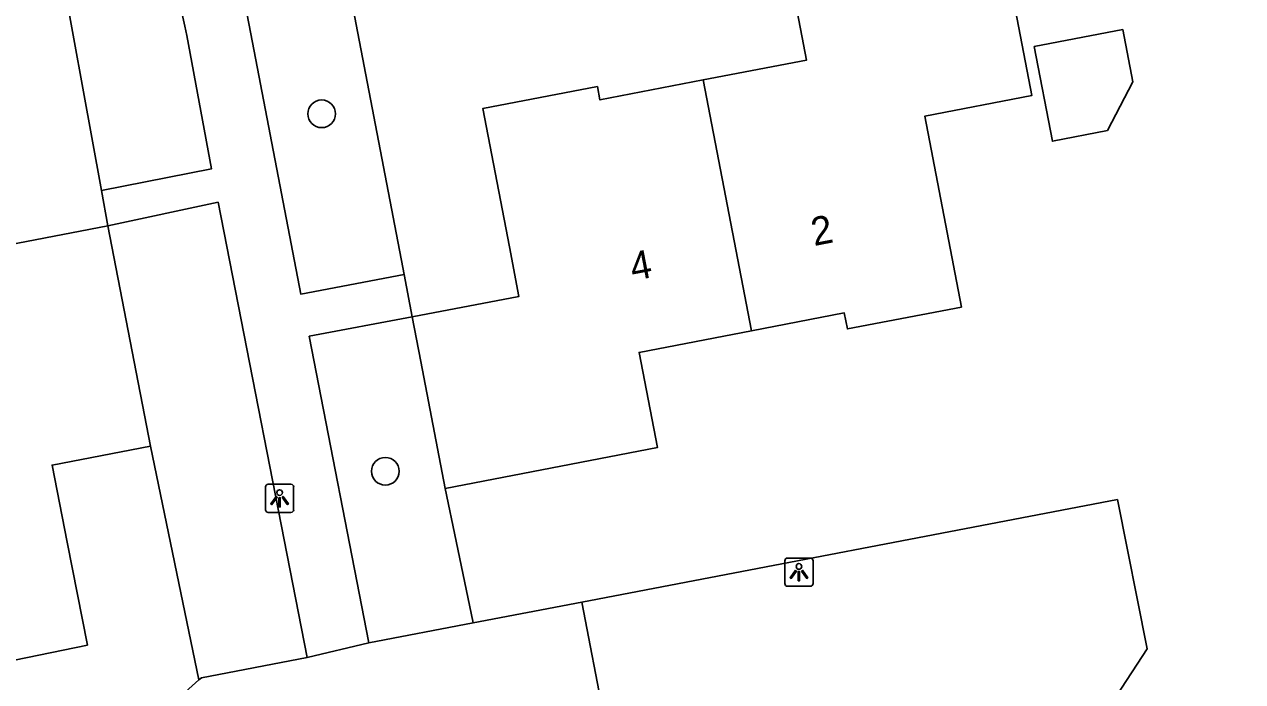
# Model space of a CAD drawing. Extents: x 157663 to 158496, y 379212 to 380934.
# Drawn here: x 158348.74 to 158391.83, y 380495.07 to 380518.31 of the extents above; entities that cross this region are included whole.
import ezdxf

# ---------------------------------------------------------------- set-up
doc = ezdxf.new("R2010")
doc.units = 0
for name, color, linetype in [('IMGEO_Boom', 7, 'Continuous'), ('IMGEO_Groenvoorziening', 7, 'Continuous'), ('IMGEO_Hek', 7, 'Continuous'), ('IMGEO_Lichtpunt', 7, 'Continuous'), ('IMGEO_Pand', 7, 'Continuous'), ('IMGEO_Pand_nummerreeks', 7, 'Continuous'), ('IMGEO_Voetpad_open', 7, 'Continuous')]:
    doc.layers.add(name, color=color, linetype=linetype)

msp = doc.modelspace()

# ---------------------------------------------------------------- linework, layer by layer
at = {"layer": 'IMGEO_Boom'}
for centre in [(158359.256, 380515.146), (158361.507, 380502.51)]:
    msp.add_circle(centre, 0.489, dxfattribs=at)
at = {"layer": 'IMGEO_Groenvoorziening'}
for points in [[(158362.172, 380509.465), (158362.125, 380509.711), (158359.11, 380525.427)], [(158351.473, 380512.429), (158349.828, 380521.424), (158348.835, 380522.437)], [(158354.917, 380495.131), (158353.2, 380503.398)], [(158363.628, 380501.901), (158364.015, 380500.041), (158364.616, 380497.15)]]:
    msp.add_lwpolyline(points, dxfattribs=at)
at = {"layer": 'IMGEO_Hek'}
msp.add_lwpolyline([(158391.091, 380481.923), (158382.675, 380487.376), (158388.452, 380496.229), (158387.396, 380501.51)], dxfattribs=at)
at = {"layer": 'IMGEO_Lichtpunt'}
for p, q in [((158357.27, 380501.955), (158357.27, 380501.148)), ((158357.27, 380501.955), (158357.27, 380501.148)), ((158358.172, 380502.05), (158357.364, 380502.05)), ((158358.172, 380502.05), (158357.364, 380502.05)), ((158358.266, 380501.148), (158358.266, 380501.955)), ((158358.266, 380501.148), (158358.266, 380501.955)), ((158357.364, 380501.054), (158358.172, 380501.054)), ((158357.364, 380501.054), (158358.172, 380501.054)), ((158375.637, 380499.345), (158375.637, 380498.538)), ((158375.637, 380499.345), (158375.637, 380498.538)), ((158376.539, 380499.44), (158375.731, 380499.44)), ((158376.539, 380499.44), (158375.731, 380499.44)), ((158376.633, 380498.538), (158376.633, 380499.345)), ((158376.633, 380498.538), (158376.633, 380499.345)), ((158375.731, 380498.444), (158376.539, 380498.444)), ((158375.731, 380498.444), (158376.539, 380498.444))]:
    msp.add_line(p, q, dxfattribs=at)
for points in [[(158357.644, 380501.619), (158357.683, 380501.591), (158357.495, 380501.329), (158357.457, 380501.356), (158357.644, 380501.619)], [(158357.746, 380501.571), (158357.793, 380501.571), (158357.793, 380501.249), (158357.746, 380501.249), (158357.746, 380501.571)], [(158357.856, 380501.591), (158357.894, 380501.618), (158358.081, 380501.356), (158358.042, 380501.328), (158357.856, 380501.591)], [(158376.011, 380499.009), (158376.05, 380498.981), (158375.862, 380498.719), (158375.824, 380498.746), (158376.011, 380499.009)], [(158376.113, 380498.961), (158376.16, 380498.961), (158376.16, 380498.639), (158376.113, 380498.639), (158376.113, 380498.961)], [(158376.223, 380498.981), (158376.261, 380499.008), (158376.448, 380498.746), (158376.409, 380498.718), (158376.223, 380498.981)]]:
    msp.add_lwpolyline(points, dxfattribs=at)
for centre in [(158357.769, 380501.753), (158376.136, 380499.143)]:
    msp.add_circle(centre, 0.0994, dxfattribs=at)
for centre, start, end in [((158357.364, 380501.955), 90, 180), ((158357.364, 380501.955), 90, 180), ((158358.172, 380501.955), 0, 90), ((158358.172, 380501.955), 0, 90), ((158357.364, 380501.148), 180, 270), ((158357.364, 380501.148), 180, 270), ((158358.172, 380501.148), 270, 0), ((158358.172, 380501.148), 270, 360), ((158375.731, 380499.345), 90, 180), ((158375.731, 380499.345), 90, 180), ((158376.539, 380499.345), 0, 90), ((158376.539, 380499.345), 0, 90), ((158375.731, 380498.538), 180, 270), ((158375.731, 380498.538), 180, 270), ((158376.539, 380498.538), 270, 0), ((158376.539, 380498.538), 270, 360)]:
    msp.add_arc(centre, 0.0946, start, end, dxfattribs=at)
at = {"layer": 'IMGEO_Pand'}
for points in [[(158372.752, 380516.343), (158376.407, 380517.047), (158375.753, 380520.441), (158383.199, 380521.875), (158384.371, 380515.791), (158380.582, 380515.062), (158381.881, 380508.316), (158377.849, 380507.539), (158377.739, 380508.108), (158374.457, 380507.476)], [(158387.585, 380518.122), (158387.941, 380516.274), (158387.043, 380514.551), (158385.101, 380514.177), (158384.457, 380517.52), (158387.585, 380518.122)], [(158362.46, 380507.964), (158366.233, 380508.691), (158365.896, 380510.438), (158364.954, 380515.328), (158369.008, 380516.109), (158369.098, 380515.639), (158372.752, 380516.343)], [(158372.752, 380516.343), (158374.457, 380507.476)], [(158353.2, 380503.398), (158349.721, 380502.728), (158350.257, 380500), (158350.971, 380496.361), (158343.222, 380494.765), (158342.196, 380500), (158341.375, 380504.19), (158345.381, 380504.962), (158345.016, 380506.859), (158346.5, 380507.145), (158345.935, 380510.075), (158351.7, 380511.185)], [(158351.7, 380511.185), (158353.2, 380503.398)], [(158362.46, 380507.964), (158362.763, 380506.393), (158363.628, 380501.901)], [(158374.457, 380507.476), (158370.48, 380506.71), (158371.129, 380503.345), (158363.628, 380501.901)]]:
    msp.add_lwpolyline(points, dxfattribs=at)
at = {"layer": 'IMGEO_Voetpad_open'}
for points in [[(158362.172, 380509.465), (158358.515, 380508.772), (158356.751, 380517.973)], [(158351.473, 380512.429), (158355.362, 380513.201), (158354.544, 380517.592)], [(158351.7, 380511.185), (158351.473, 380512.429)], [(158351.7, 380511.185), (158355.591, 380512.02), (158358.744, 380495.92)], [(158362.46, 380507.964), (158362.172, 380509.465)], [(158360.929, 380496.444), (158358.818, 380507.28), (158362.46, 380507.964)], [(158402.85, 380476.983), (158399.153, 380476.703), (158391.091, 380481.923), (158382.675, 380487.376), (158388.452, 380496.229), (158387.396, 380501.51), (158368.462, 380497.886)], [(158368.462, 380497.886), (158364.616, 380497.15)], [(158368.685, 380492.845), (158369.249, 380493.776), (158368.462, 380497.886)], [(158364.616, 380497.15), (158360.929, 380496.444)], [(158358.744, 380495.92), (158360.929, 380496.444)], [(158358.744, 380495.92), (158355.005, 380495.209), (158354.917, 380495.131)], [(158316.229, 380460.36), (158354.917, 380495.131)]]:
    msp.add_lwpolyline(points, dxfattribs=at)
for centre, radius, start, end in [((158334.971, 380514.214), 22.102, 9.7924, 25.2761), ((158334.983, 380514.216), 19.851, 9.7929, 25.0642)]:
    msp.add_arc(centre, radius, start, end, dxfattribs=at)

# ---------------------------------------------------------------- texts
at = {"layer": 'IMGEO_Pand_nummerreeks'}
for s, p in [('2', (158376.67, 380510.469)), ('4', (158370.264, 380509.236))]:
    msp.add_text(s, height=1, rotation=10.901, dxfattribs=at).set_placement(p)

doc.saveas('drawing.dxf')
